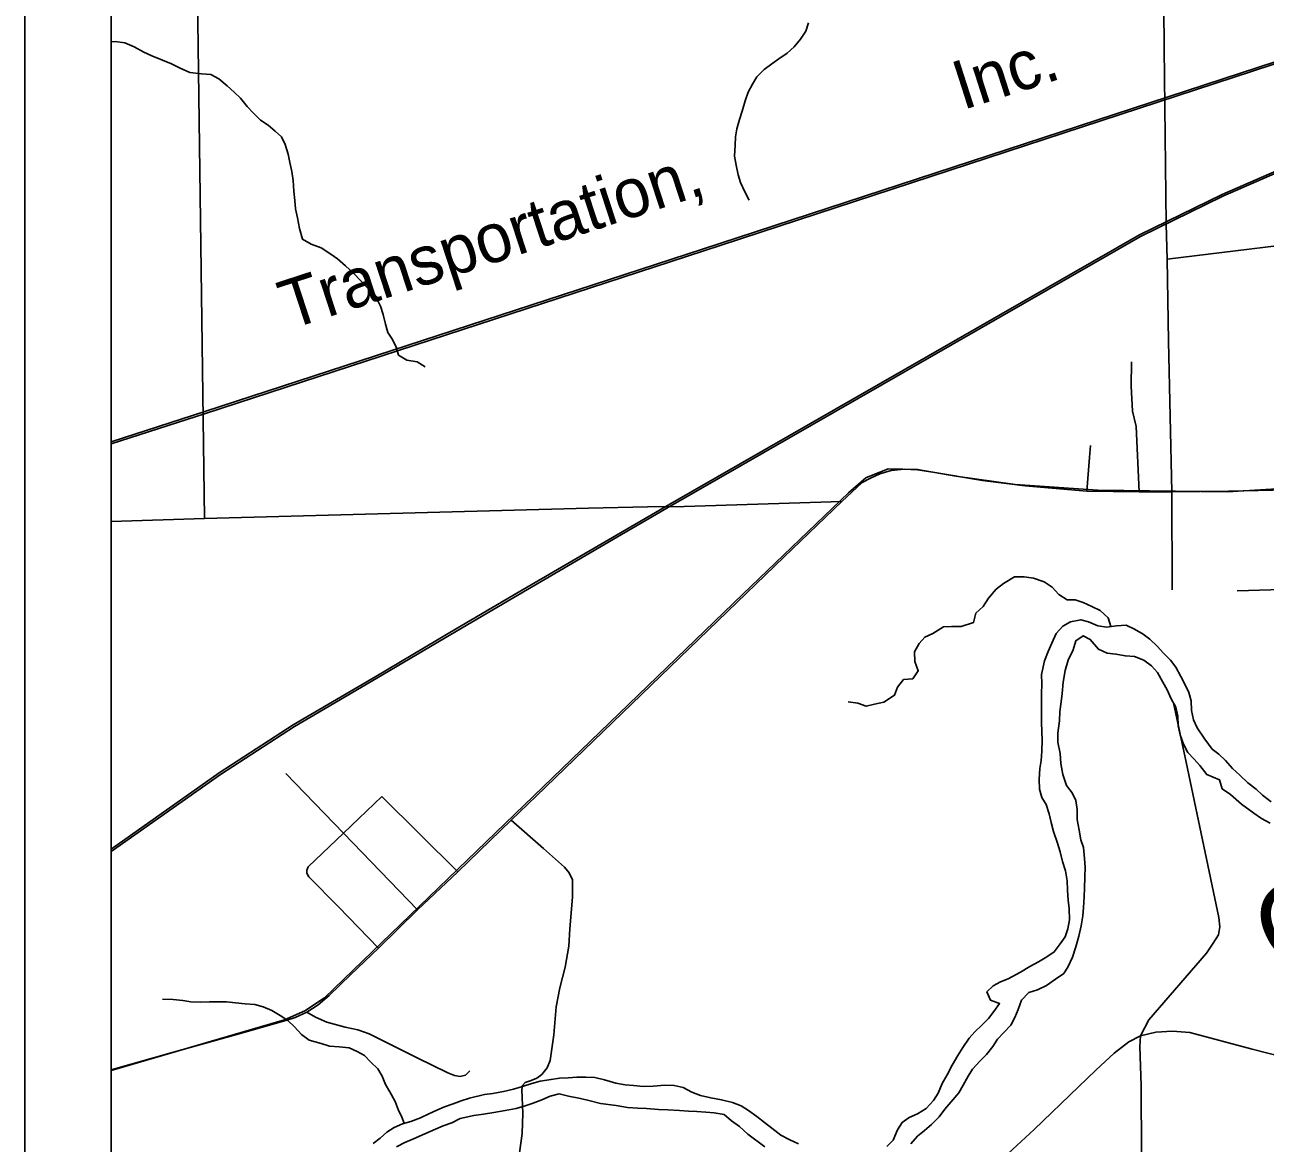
# Model space of a CAD drawing. Extents: x -5.4 to 71.3, y -12 to 22.
# Drawn here: x 2 to 3.436, y 15.003 to 16.298 of the extents above; entities that cross this region are included whole.
import ezdxf

# ---------------------------------------------------------------- set-up
doc = ezdxf.new("R2010")
doc.units = 0
for name, color, linetype in [('GM_X_City_Street', 7, 'Continuous'), ('GM_X_Minor_River', 7, 'Continuous'), ('GM_X_Minor_River_Text', 7, 'Continuous'), ('GM_X_Rail_Line', 7, 'Continuous'), ('GM_X_Rail_Line_Text', 7, 'Continuous'), ('GM_X_US_Route', 7, 'Continuous'), ('PM_X_Surveyed_Line', 7, 'Continuous'), ('SH_Cut_Line', 7, 'Continuous'), ('SH_Data', 7, 'Continuous')]:
    doc.layers.add(name, color=color, linetype=linetype)

msp = doc.modelspace()

# ---------------------------------------------------------------- linework, layer by layer
at = {"layer": 'GM_X_City_Street'}
for p, q in [((2.2082, 15.7262), (2.1981, 16.4614)), ((3.3286, 15.6436), (3.3279, 15.757)), ((2.1, 15.7225), (2.2082, 15.7262)), ((3.3445, 15.444), (3.3299, 15.5128)), ((2.5012, 15.317), (2.4134, 15.4042))]:
    msp.add_line(p, q, dxfattribs=at)
for points in [[(3.3279, 15.757), (3.3243, 15.9316), (3.3228, 16.0266), (3.3213, 16.0671), (3.3192, 16.2707), (3.3188, 16.3174)], [(3.3228, 16.0266), (3.5313, 16.0518), (3.596, 16.061), (3.7425, 16.0794), (3.7984, 16.0865), (3.8172, 16.089), (3.8618, 16.0944), (3.8744, 16.0969), (3.9649, 16.1082), (3.9807, 16.1111), (3.9949, 16.1134), (4.0477, 16.1324), (4.0996, 16.1507), (4.159, 16.1613), (4.2334, 16.1737), (4.2795, 16.1806)], [(3.2901, 15.7569), (3.2868, 15.8327), (3.2823, 15.8504), (3.2809, 15.8794), (3.2814, 15.9075)], [(3.2296, 15.7577), (3.2328, 15.7969), (3.2338, 15.8105)], [(2.2082, 15.7262), (2.6528, 15.738), (2.721, 15.7395), (2.7635, 15.74), (2.946, 15.7459)], [(3.4036, 15.6424), (3.4816, 15.6445), (3.495, 15.6424), (3.5092, 15.6353), (3.5275, 15.6291)], [(3.2919, 15.127), (3.3014, 15.1456), (3.3683, 15.2226), (3.376, 15.2342), (3.3822, 15.244), (3.3835, 15.2533), (3.3826, 15.264), (3.3445, 15.444)], [(2.4548, 15.2727), (2.369, 15.3616), (2.3023, 15.4309)], [(2.4134, 15.4042), (2.369, 15.3616), (2.3279, 15.3227), (2.3264, 15.3187)], [(2.5679, 14.9553), (2.5757, 15.014), (2.5767, 15.0372), (2.5756, 15.0644), (2.5762, 15.0695), (2.5794, 15.0727), (2.5863, 15.0753), (2.5929, 15.0779), (2.5985, 15.0823), (2.6046, 15.0898), (2.6081, 15.0982), (2.6127, 15.1281), (2.6153, 15.1604), (2.6195, 15.1826), (2.6257, 15.2066), (2.6297, 15.2308), (2.6312, 15.251), (2.6341, 15.2876), (2.6343, 15.3076), (2.6303, 15.3158), (2.625, 15.3222), (2.6007, 15.3439), (2.5632, 15.3768)], [(2.4094, 15.2286), (2.3632, 15.2762), (2.329, 15.3109), (2.3265, 15.3152), (2.3264, 15.3187)], [(2.3265, 15.1544), (2.3365, 15.1485), (2.3498, 15.1427), (2.371, 15.1369), (2.3854, 15.1338), (2.3988, 15.1293), (2.4542, 15.1016), (2.4897, 15.0841), (2.4975, 15.0811), (2.504, 15.0799), (2.5104, 15.0815), (2.5153, 15.0864)], [(3.5451, 15.0797), (3.4209, 15.1113), (3.349, 15.1307), (3.3287, 15.1322), (3.3096, 15.1313), (3.2919, 15.127), (3.2784, 15.1201), (3.2611, 15.1069), (3.2401, 15.087), (3.22, 15.0678), (3.1688, 15.0185), (3.1033, 14.9584)], [(3.2989, 14.1), (3.2986, 14.1255), (3.2986, 14.2351), (3.2986, 14.3499), (3.2964, 14.5959), (3.2954, 14.7147), (3.2953, 14.7963), (3.2928, 14.9894), (3.2927, 15.0693), (3.2916, 15.0918), (3.2911, 15.1147), (3.2919, 15.127)]]:
    msp.add_lwpolyline(points, dxfattribs=at)
at = {"layer": 'GM_X_Minor_River'}
for points in [[(2.9074, 16.3001), (2.9042, 16.2905), (2.8982, 16.2813), (2.8908, 16.2724), (2.8825, 16.265), (2.8732, 16.2584), (2.8649, 16.2529), (2.8559, 16.2462), (2.8477, 16.2377), (2.8425, 16.2292), (2.8377, 16.22), (2.8341, 16.2097), (2.8305, 16.1978), (2.8276, 16.1882), (2.8243, 16.1775), (2.823, 16.168), (2.8224, 16.1584), (2.8218, 16.1459), (2.8235, 16.1352), (2.826, 16.1243), (2.8288, 16.1152), (2.8336, 16.1046), (2.8387, 16.0948)], [(2.1, 16.278), (2.1046, 16.2784), (2.116, 16.2771), (2.1268, 16.2724), (2.1379, 16.2661), (2.1471, 16.2621), (2.1593, 16.257), (2.1697, 16.2526), (2.18, 16.2475), (2.1911, 16.2428), (2.2045, 16.2411), (2.2155, 16.2402), (2.2247, 16.2354), (2.2343, 16.2272), (2.2424, 16.2198), (2.2498, 16.213), (2.2575, 16.2033), (2.2649, 16.1954), (2.273, 16.1876), (2.2819, 16.1817), (2.29, 16.1746), (2.2973, 16.1683), (2.3016, 16.1592), (2.3048, 16.1482), (2.3069, 16.1384), (2.309, 16.1281), (2.3107, 16.1175), (2.3116, 16.1054), (2.3126, 16.0943), (2.3135, 16.0848), (2.3156, 16.0742), (2.3181, 16.0621), (2.3217, 16.0496), (2.3317, 16.0437), (2.3431, 16.0397), (2.3543, 16.0323), (2.362, 16.0268), (2.3712, 16.0189), (2.3801, 16.0107), (2.3894, 16.001), (2.3964, 15.9935), (2.406, 15.9838), (2.4119, 15.9721), (2.4148, 15.9623), (2.4176, 15.9513), (2.4204, 15.9415), (2.4259, 15.9336), (2.4298, 15.9245), (2.4326, 15.9154), (2.4423, 15.9095), (2.4541, 15.9075), (2.4637, 15.9019)], [(3.2575, 15.601), (3.2543, 15.6109), (3.245, 15.6195), (3.2354, 15.6243), (3.2255, 15.629), (3.2163, 15.6319), (3.2068, 15.6321), (3.1972, 15.638), (3.1894, 15.6466), (3.1802, 15.6529), (3.168, 15.6569), (3.1569, 15.6586), (3.1459, 15.6587), (3.1331, 15.6509), (3.1245, 15.6442), (3.1159, 15.6338), (3.1096, 15.6242), (3.101, 15.6164), (3.0985, 15.6057), (3.0841, 15.6009), (3.0731, 15.601), (3.0636, 15.6005), (3.0512, 15.593), (3.0421, 15.5886), (3.0354, 15.5813), (3.0299, 15.5717), (3.0305, 15.5603), (3.0344, 15.5497), (3.0281, 15.5404), (3.0175, 15.5395), (3.0104, 15.5306), (3.0068, 15.5214), (2.9947, 15.5135), (2.9838, 15.511), (2.9743, 15.5086), (2.9644, 15.5122), (2.9533, 15.5139)], [(3.4429, 15.398), (3.4332, 15.4058), (3.4255, 15.4125), (3.4162, 15.4199), (3.4066, 15.4289), (3.3984, 15.4367), (3.3903, 15.446), (3.3825, 15.4531), (3.3748, 15.459), (3.3662, 15.4707), (3.3572, 15.4838), (3.3533, 15.4929), (3.3508, 15.5038), (3.3506, 15.5149), (3.3477, 15.5247), (3.343, 15.5341), (3.3383, 15.5432), (3.3327, 15.5541), (3.3265, 15.5619), (3.3184, 15.5702), (3.311, 15.5784), (3.3025, 15.5862), (3.2947, 15.5921), (3.2848, 15.598), (3.2752, 15.6024), (3.2638, 15.6018), (3.2528, 15.6004), (3.2425, 15.6017), (3.2317, 15.6065), (3.2226, 15.6089), (3.2108, 15.6064), (3.2018, 15.6013), (3.1943, 15.5928), (3.1892, 15.5816), (3.1848, 15.572), (3.1805, 15.5613), (3.177, 15.5453), (3.1776, 15.5346), (3.177, 15.5232), (3.1772, 15.5122), (3.1771, 15.5004), (3.1773, 15.4893), (3.1774, 15.4798), (3.178, 15.4692), (3.1775, 15.4566), (3.1766, 15.4459), (3.1752, 15.4364), (3.1743, 15.4238), (3.1749, 15.4128), (3.1774, 15.403), (3.1825, 15.3947), (3.1861, 15.3841), (3.1882, 15.3739), (3.191, 15.3637), (3.1955, 15.3501), (3.1987, 15.3399), (3.2016, 15.3289), (3.2048, 15.3179), (3.2069, 15.3066), (3.2071, 15.2955), (3.2081, 15.2841), (3.2091, 15.2743), (3.2097, 15.2613), (3.2076, 15.251), (3.2044, 15.2415), (3.1988, 15.2334), (3.1918, 15.2241), (3.1835, 15.2186), (3.1737, 15.2127), (3.1636, 15.2072), (3.153, 15.2005), (3.1387, 15.193), (3.1297, 15.1894), (3.121, 15.185), (3.1139, 15.178), (3.1179, 15.1682), (3.1286, 15.1642), (3.122, 15.155), (3.1156, 15.1469), (3.1082, 15.1391), (3.1, 15.1317), (3.0933, 15.1243), (3.0862, 15.1136), (3.0803, 15.1043), (3.0737, 15.0931), (3.0678, 15.0816), (3.0623, 15.0716), (3.0576, 15.0605), (3.052, 15.052)], [(3.1416, 15.1394), (3.1464, 15.1482), (3.1501, 15.1574), (3.154, 15.1682), (3.1626, 15.1771), (3.1724, 15.1803), (3.183, 15.1851), (3.1935, 15.1926), (3.2029, 15.1992), (3.2081, 15.2073), (3.2132, 15.2181), (3.2168, 15.2299), (3.2203, 15.2425), (3.2231, 15.2544), (3.2248, 15.2658), (3.2258, 15.2757), (3.2267, 15.2879), (3.2269, 15.2978), (3.2274, 15.3108), (3.2276, 15.3222), (3.227, 15.3324), (3.2256, 15.345), (3.2228, 15.354), (3.2207, 15.365), (3.2185, 15.3776), (3.2183, 15.389), (3.217, 15.3996), (3.2126, 15.4082), (3.206, 15.4169), (3.202, 15.4297), (3.1994, 15.4422), (3.1988, 15.454), (3.1959, 15.4669), (3.1961, 15.4775), (3.1978, 15.4916), (3.1983, 15.5027), (3.2, 15.5138), (3.201, 15.5233), (3.2022, 15.5366), (3.2047, 15.55), (3.2082, 15.5619), (3.2137, 15.5741), (3.2169, 15.5845), (3.2252, 15.5904), (3.2336, 15.586), (3.243, 15.5747), (3.2533, 15.57), (3.2632, 15.5691), (3.2743, 15.567), (3.285, 15.5661), (3.2957, 15.5621), (3.3046, 15.5554), (3.3116, 15.5476), (3.3175, 15.5367), (3.3226, 15.5276), (3.3273, 15.5171), (3.3325, 15.5077), (3.3349, 15.4971), (3.3355, 15.486), (3.3376, 15.4754), (3.3416, 15.4649), (3.3467, 15.4551), (3.3537, 15.4472), (3.3603, 15.4401), (3.3685, 15.4296), (3.3831, 15.4235), (3.3863, 15.4132), (3.396, 15.4066), (3.4087, 15.3951), (3.423, 15.3847), (3.4318, 15.3788), (3.4418, 15.3733)], [(2.439, 15.0256), (2.4392, 15.0256), (2.4364, 15.0326), (2.4321, 15.0416), (2.4289, 15.0507), (2.4226, 15.062), (2.4175, 15.0706), (2.4136, 15.0804), (2.4089, 15.0887), (2.4008, 15.0965), (2.3934, 15.104), (2.385, 15.1088), (2.3754, 15.1132), (2.364, 15.1141), (2.3529, 15.115), (2.343, 15.1179), (2.3292, 15.1218), (2.3204, 15.1285), (2.3122, 15.1374), (2.3045, 15.1445), (2.2957, 15.1504), (2.2861, 15.1563), (2.2761, 15.1607), (2.2662, 15.1632), (2.2551, 15.1641), (2.2441, 15.165), (2.2334, 15.1664), (2.2239, 15.1662), (2.214, 15.1664), (2.203, 15.1661), (2.1924, 15.1663), (2.1829, 15.1677), (2.1718, 15.169), (2.1593, 15.1695)], [(3.026, 15.002), (3.0334, 15.0106), (3.0417, 15.0172), (3.0499, 15.0242), (3.0585, 15.0331), (3.0652, 15.042), (3.0745, 15.0528), (3.0815, 15.061), (3.0863, 15.0698), (3.0922, 15.0802), (3.0974, 15.0883), (3.1063, 15.098), (3.1134, 15.1054), (3.1208, 15.1146), (3.126, 15.1231), (3.1334, 15.1309), (3.1416, 15.1394)], [(2.8959, 15.0017), (2.8856, 15.0064), (2.8752, 15.0119), (2.8648, 15.0201), (2.8563, 15.0267), (2.8474, 15.0334), (2.8378, 15.0404), (2.8293, 15.046), (2.8194, 15.0496), (2.8067, 15.0527), (2.7941, 15.0551), (2.7823, 15.0579), (2.7724, 15.0615), (2.7624, 15.0671), (2.7517, 15.0695), (2.741, 15.0697), (2.7277, 15.0686), (2.7159, 15.0684), (2.7049, 15.0693), (2.695, 15.0702), (2.6843, 15.0723), (2.6713, 15.0759), (2.6598, 15.0787), (2.6496, 15.0792), (2.6393, 15.079), (2.629, 15.0784), (2.6192, 15.0778), (2.6093, 15.0765), (2.5968, 15.0743), (2.587, 15.0719), (2.5764, 15.0682), (2.5658, 15.0653), (2.5541, 15.0624), (2.5419, 15.0603), (2.5321, 15.0589), (2.515, 15.0548), (2.5052, 15.0516), (2.4958, 15.0483), (2.4859, 15.0447), (2.4769, 15.0407), (2.4678, 15.0367), (2.458, 15.032), (2.4471, 15.0279), (2.4373, 15.0251), (2.4275, 15.0207), (2.4192, 15.0152), (2.4113, 15.0086), (2.4035, 15.0023)], [(2.4305, 14.9983), (2.44, 15.0034), (2.4501, 15.0078), (2.463, 15.0134), (2.4754, 15.019), (2.4845, 15.0226), (2.4943, 15.0262), (2.5041, 15.031), (2.52, 15.0347), (2.531, 15.0361), (2.5431, 15.0383), (2.556, 15.0404), (2.5689, 15.0426), (2.578, 15.0454), (2.5874, 15.0487), (2.5987, 15.0527), (2.6082, 15.0571), (2.6188, 15.0596), (2.6295, 15.0571), (2.6432, 15.0544), (2.6547, 15.0516), (2.6665, 15.0487), (2.6848, 15.0461), (2.6978, 15.0441), (2.7096, 15.0432), (2.7199, 15.0426), (2.7336, 15.0417), (2.7446, 15.0412), (2.7579, 15.0403), (2.7686, 15.0398), (2.7781, 15.0392), (2.7884, 15.0387), (2.7983, 15.0377), (2.8097, 15.0357), (2.8182, 15.0286), (2.8275, 15.022), (2.8372, 15.013), (2.8568, 14.9982)], [(3.052, 15.052), (3.0435, 15.0427), (3.0337, 15.0364), (3.0239, 15.0324), (3.016, 15.0266), (3.0105, 15.0181), (3.0054, 15.0062), (2.9979, 14.9988)]]:
    msp.add_lwpolyline(points, dxfattribs=at)
at = {"layer": 'GM_X_Minor_River_Text'}
msp.add_lwpolyline([(2.1, 16.5529), (2.1, 14.1), (6.9755, 14.1)], dxfattribs=at)
at = {"layer": 'GM_X_Rail_Line'}
for points in [[(2.1, 15.8148), (2.2084, 15.85), (2.7845, 16.0381), (3.5525, 16.2895), (3.9999, 16.4363), (4.2764, 16.5289), (4.4956, 16.5982), (4.5851, 16.6274), (4.6324, 16.6405), (4.714, 16.6576), (4.912, 16.6969), (5.1624, 16.7441), (5.4756, 16.8049), (5.8762, 16.8809), (6.3808, 16.9775), (6.9091, 17.0789)], [(2.1, 15.8124), (2.2091, 15.8478), (2.7852, 16.0359), (3.5533, 16.2873), (4.0006, 16.4341), (4.2771, 16.5267), (4.4963, 16.5961), (4.5857, 16.6252), (4.633, 16.6383), (4.7144, 16.6554), (4.9125, 16.6946), (5.1628, 16.7419), (5.476, 16.8027), (5.8766, 16.8787), (6.3813, 16.9752), (6.9095, 17.0766)], [(2.1, 15.3432), (2.2251, 15.4314), (2.3109, 15.4873), (2.4064, 15.5432), (2.4922, 15.5939), (2.5649, 15.6368), (2.6851, 15.707), (2.7468, 15.7427), (3.2906, 16.0546), (3.3862, 16.1015), (3.4492, 16.1288), (3.5165, 16.1567)], [(2.1, 15.3404), (2.2264, 15.4295), (2.3121, 15.4853), (2.4076, 15.5412), (2.4934, 15.5919), (2.5661, 15.6348), (2.6863, 15.705), (2.748, 15.7407), (3.2917, 16.0526), (3.3871, 16.0994), (3.4501, 16.1267)], [(2.1, 15.0867), (2.3008, 15.1456), (2.3241, 15.1557), (2.3468, 15.1708), (2.8314, 15.6385), (2.9537, 15.7558), (2.9738, 15.7734), (2.9997, 15.7835), (3.0337, 15.7829), (3.0778, 15.7753), (3.1465, 15.7653), (3.2423, 15.7589), (3.3922, 15.7571), (3.6746, 15.7741)]]:
    msp.add_lwpolyline(points, dxfattribs=at)
at = {"layer": 'GM_X_US_Route'}
msp.add_lwpolyline([(2.1, 15.0875), (2.1723, 15.108), (2.244, 15.1281), (2.3022, 15.1446), (2.3129, 15.1481), (2.3265, 15.1544), (2.3398, 15.1629), (2.3525, 15.1738), (2.3774, 15.1979), (2.4094, 15.2286), (2.4548, 15.2727), (2.5012, 15.317), (2.5632, 15.3768), (2.592, 15.4046), (2.8022, 15.6076), (2.8793, 15.6817), (2.946, 15.7459), (2.9695, 15.7678), (2.979, 15.7729), (2.9898, 15.7778), (3.0032, 15.7816), (3.0183, 15.7834), (3.0336, 15.7826), (3.0536, 15.7794), (3.1088, 15.7702), (3.1581, 15.7638), (3.2296, 15.7577), (3.2901, 15.7569), (3.3279, 15.757), (3.3937, 15.7576), (3.4793, 15.7596)], dxfattribs=at)
at = {"layer": 'PM_X_Surveyed_Line'}
msp.add_lwpolyline([(3.5242, 17.1246), (3.4004, 17.1035), (3.1751, 17.0399), (3.1341, 17.0224), (3.1261, 17.0171), (3.057, 16.991), (3.0057, 16.9701), (2.9111, 16.9873), (2.7964, 16.8992), (2.7089, 16.8312), (2.5334, 16.7629), (2.4684, 16.733), (2.3586, 16.6775), (2.1, 16.5617), (2.1, 14.1), (6.9757, 14.1)], dxfattribs=at)
at = {"layer": 'SH_Cut_Line'}
msp.add_lwpolyline([(2.1, 16.5529), (2.1, 14.1), (6.9755, 14.1)], dxfattribs=at)
at = {"layer": 'SH_Data'}
for p, q in [((2, 21), (2, 14)), ((2.1, 20.9), (2.1, 14.1))]:
    msp.add_line(p, q, dxfattribs=at)

# ---------------------------------------------------------------- texts
at = {"layer": 'GM_X_Minor_River_Text'}
msp.add_text('Conneaut Creek', height=0.094798, rotation=25.9394, dxfattribs=at).set_placement((3.4528, 15.1958))
at = {"layer": 'GM_X_Rail_Line_Text'}
for s, height, rotation, p in [('Inc.', 0.05663, 17.7967, (3.0857, 16.1989)), ('Transportation,', 0.056629, 18.0895, (2.3061, 15.9444))]:
    msp.add_text(s, height=height, rotation=rotation, dxfattribs=at).set_placement(p)

doc.saveas('drawing.dxf')
